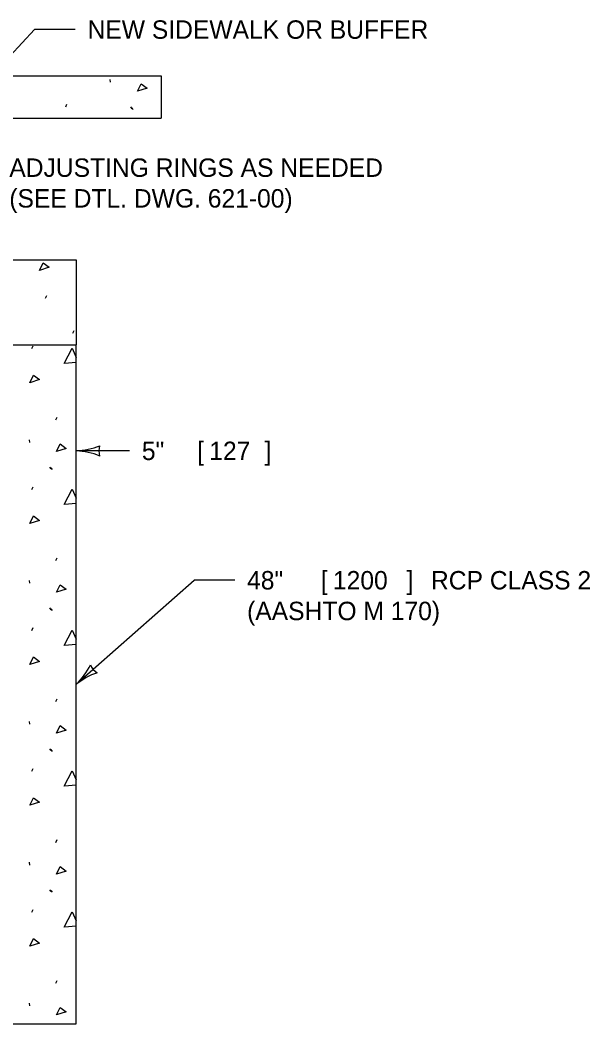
# Model space of a CAD drawing. Extents: x 49991.4 to 50057, y 49987.6 to 50011.4.
# Drawn here: x 50045.28 to 50047.136, y 49989.634 to 49992.904 of the extents above; entities that cross this region are included whole.
import ezdxf

# ---------------------------------------------------------------- set-up
doc = ezdxf.new("R2010")
doc.units = 0
for name, color, linetype in [('Level 1', 7, 'Continuous'), ('Level 2', 7, 'Continuous'), ('Level 3', 7, 'Continuous')]:
    doc.layers.add(name, color=color, linetype=linetype)

msp = doc.modelspace()

# ---------------------------------------------------------------- linework, layer by layer
at = {"layer": 'Level 1'}
for p, q in [((50044.6334, 49992.722), (50045.7396, 49992.722)), ((50045.7396, 49992.722), (50045.7396, 49992.5838)), ((50045.5726, 49992.7102), (50045.5736, 49992.7014)), ((50045.4284, 49992.6209), (50045.4324, 49992.6298)), ((50045.6396, 49992.6209), (50045.6436, 49992.615)), ((50045.6436, 49992.6187), (50045.6475, 49992.6128)), ((50044.6334, 49992.5838), (50045.7396, 49992.5838)), ((50044.6334, 49992.1229), (50045.463, 49992.1229)), ((50045.463, 49992.1229), (50045.463, 49991.8463)), ((50045.3627, 49991.9977), (50045.3667, 49992.0066)), ((50045.4521, 49991.8838), (50045.456, 49991.8926)), ((50044.6334, 49991.8463), (50045.463, 49991.8463)), ((50045.3182, 49991.8337), (50045.3221, 49991.8425)), ((50045.463, 49989.6339), (50045.463, 49991.8463)), ((50045.463, 49991.7879), (50045.4243, 49991.7846)), ((50045.3968, 49991.6019), (50045.4007, 49991.6107)), ((50045.3091, 49991.5369), (50045.3101, 49991.5281)), ((50045.3761, 49991.4476), (50045.3801, 49991.4417)), ((50045.3801, 49991.4454), (50045.384, 49991.4395)), ((50045.3182, 49991.3748), (50045.3221, 49991.3837)), ((50045.463, 49991.329), (50045.4243, 49991.3257)), ((50045.3968, 49991.143), (50045.4007, 49991.1518)), ((50045.3091, 49991.078), (50045.3101, 49991.0692)), ((50045.3761, 49990.9888), (50045.3801, 49990.9829)), ((50045.3801, 49990.9865), (50045.384, 49990.9806)), ((50045.3182, 49990.9159), (50045.3221, 49990.9248)), ((50045.463, 49990.8701), (50045.4243, 49990.8668)), ((50045.3968, 49990.6841), (50045.4007, 49990.6929)), ((50045.3091, 49990.6192), (50045.3101, 49990.6103)), ((50045.3761, 49990.5299), (50045.3801, 49990.524)), ((50045.3801, 49990.5276), (50045.384, 49990.5217)), ((50045.3182, 49990.4571), (50045.3221, 49990.4659)), ((50045.463, 49990.4112), (50045.4243, 49990.408)), ((50045.3968, 49990.2252), (50045.4007, 49990.2341)), ((50045.3091, 49990.1603), (50045.3101, 49990.1514)), ((50045.3761, 49990.071), (50045.3801, 49990.0651)), ((50045.3801, 49990.0688), (50045.384, 49990.0629)), ((50045.3182, 49989.9982), (50045.3221, 49990.007)), ((50045.463, 49989.9524), (50045.4243, 49989.9491)), ((50045.3968, 49989.7664), (50045.4007, 49989.7752)), ((50045.3091, 49989.7014), (50045.3101, 49989.6926)), ((50042.6975, 49989.6339), (50045.463, 49989.6339))]:
    msp.add_line(p, q, dxfattribs=at)
for points in [[(50045.6622, 49992.672), (50045.674, 49992.6966), (50045.6937, 49992.6818), (50045.6622, 49992.672)], [(50045.3433, 49992.0886), (50045.3551, 49992.1132), (50045.3747, 49992.0984), (50045.3433, 49992.0886)], [(50045.4233, 49991.7846), (50045.4498, 49991.8347), (50045.463, 49991.8051)], [(50045.3113, 49991.7227), (50045.3231, 49991.7472), (50045.3427, 49991.7325), (50045.3113, 49991.7227)], [(50045.3987, 49991.4987), (50045.4105, 49991.5233), (50045.4302, 49991.5085), (50045.3987, 49991.4987)], [(50045.4233, 49991.3257), (50045.4498, 49991.3758), (50045.463, 49991.3462)], [(50045.3113, 49991.2638), (50045.3231, 49991.2884), (50045.3427, 49991.2736), (50045.3113, 49991.2638)], [(50045.3987, 49991.0398), (50045.4105, 49991.0644), (50045.4302, 49991.0497), (50045.3987, 49991.0398)], [(50045.4233, 49990.8668), (50045.4498, 49990.9169), (50045.463, 49990.8874)], [(50045.3113, 49990.8049), (50045.3231, 49990.8295), (50045.3427, 49990.8148), (50045.3113, 49990.8049)], [(50045.3987, 49990.581), (50045.4105, 49990.6055), (50045.4302, 49990.5908), (50045.3987, 49990.581)], [(50045.4233, 49990.408), (50045.4498, 49990.458), (50045.463, 49990.4285)], [(50045.3113, 49990.3461), (50045.3231, 49990.3706), (50045.3427, 49990.3559), (50045.3113, 49990.3461)], [(50045.3987, 49990.1221), (50045.4105, 49990.1466), (50045.4302, 49990.1319), (50045.3987, 49990.1221)], [(50045.4233, 49989.9491), (50045.4498, 49989.9992), (50045.463, 49989.9696)], [(50045.3113, 49989.8872), (50045.3231, 49989.9117), (50045.3427, 49989.897), (50045.3113, 49989.8872)], [(50045.3987, 49989.6632), (50045.4105, 49989.6878), (50045.4302, 49989.673), (50045.3987, 49989.6632)]]:
    msp.add_lwpolyline(points, dxfattribs=at)
at = {"layer": 'Level 3'}
for p, q in [((50045.1865, 49992.722), (50045.3269, 49992.8729)), ((50045.1865, 49992.722), (50045.3269, 49992.8729)), ((50045.4596, 49992.8729), (50045.3269, 49992.8729)), ((50045.4596, 49992.8729), (50045.3269, 49992.8729)), ((50045.6365, 49991.5006), (50045.463, 49991.5006)), ((50045.463, 49990.7401), (50045.8464, 49991.0791)), ((50045.9792, 49991.0791), (50045.8464, 49991.0791))]:
    msp.add_line(p, q, dxfattribs=at)
for centre, radius, start, end in [((50045.4515, 49991.7333), 0.233, 272.8273, 292.0772), ((50045.5912, 49991.5006), 0.0548, 162.1388, 197.8612), ((50045.4539, 49991.2785), 0.2223, 67.456, 87.6395), ((50045.3003, 49990.9068), 0.233, 314.307, 333.5569), ((50045.5591, 49990.825), 0.0548, 203.6185, 239.3409), ((50045.6033, 49990.5676), 0.2223, 108.9357, 129.1192)]:
    msp.add_arc(centre, radius, start, end, dxfattribs=at)

# ---------------------------------------------------------------- texts
at = {"layer": 'Level 2'}
for s, p in [('NEW SIDEWALK OR BUFFER', (50045.4996, 49992.8429)), ('ADJUSTING RINGS AS NEEDED', (50045.2448, 49992.3931)), ('(SEE DTL. DWG. 621-00)', (50045.2448, 49992.2931)), ('5" ', (50045.6765, 49991.4706)), ('[', (50045.8565, 49991.4706)), ('127', (50045.8961, 49991.4706)), (']', (50046.0761, 49991.4706)), ('48" ', (50046.0192, 49991.0491)), ('[', (50046.2592, 49991.0491)), ('1200', (50046.2989, 49991.0491)), ('] ', (50046.5389, 49991.0491)), ('RCP CLASS 2', (50046.6182, 49991.0491)), ('(AASHTO M 170)', (50046.0192, 49990.9491))]:
    msp.add_text(s, height=0.06, dxfattribs=at).set_placement(p)

doc.saveas('drawing.dxf')
